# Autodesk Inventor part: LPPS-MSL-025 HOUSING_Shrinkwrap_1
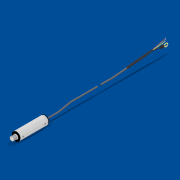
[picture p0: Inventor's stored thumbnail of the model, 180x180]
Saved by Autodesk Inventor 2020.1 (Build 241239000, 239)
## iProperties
Created: 2019-07
Part Number: LPPS-MSL-025 HOUSING_Shrinkwrap_1
Material: Generic
Document SubType Name: Modeling
Designer: J. Nielson
Density: 1 g/cm^3
Appearance: Default
Author: J. Nielson
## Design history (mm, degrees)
node "Assembly1"
body "Solid1"
node "Part1:1"
node "Part2:1"
body "Solid2"
node "Part3:1"
body "Solid3"
node "Part4:1"
body "Solid4"
node "Part5:1"
body "Solid5"
node "Part6:1"
body "Solid6"
node "Part7:1"
body "Solid7"
node "Part8:1"
body "Solid8"
node "Part9:1"
body "Solid9"
node "Part10:1"
body "Solid10"
node "Part11:1"
body "Solid11"
node "Part12:1"
body "Solid12"
node "Part13:1"
body "Solid13"
node "Part14:1"
body "Solid14"
node "Part15:1"
body "Solid15"
node "Part16:1"
body "Solid16"
node "Part17:1"
body "Solid17"
node "Part16:2"
body "Solid18"
node "Part17:2"
body "Solid19"
